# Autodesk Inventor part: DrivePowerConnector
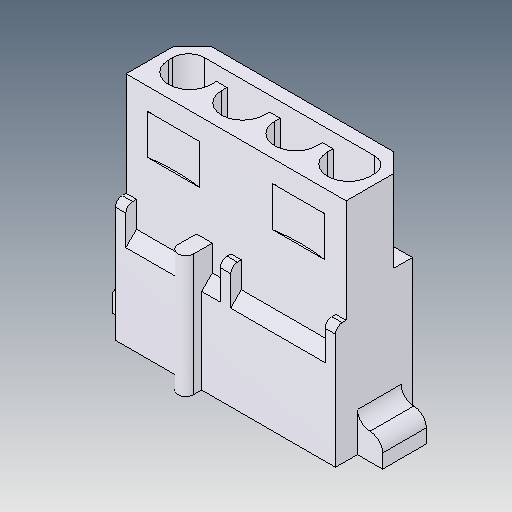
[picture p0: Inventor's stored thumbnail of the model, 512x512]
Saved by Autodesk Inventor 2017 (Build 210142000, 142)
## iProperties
Created: 2006-09
Part Number: DrivePowerConnector
Material: Generic
Document SubType Name: Modeling
Designer: DanielSeverino
Categories: <MemberInstance><Categories><Category DisplayName="" Mnemonic="CABLEANDHARNESS" InternalName="e4a7e005-5e42-4d16-b293-125e7f0d0512"><Category DisplayName="" Mne
Density: 1 g/cm^3
Appearance: Default
GlobalPropertyList: <PropertyList/>
Title: Drive Power Connector
Author: Prof. Daniel Severino
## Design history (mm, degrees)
feature "Solid1"
sketch "Sketch1"
  geometry: C1 r 1.125 at (9.9, -4.195) reference; C2 r 1.125 at (4.82, -4.195) reference; C3 r 1.125 at (-0.26, -4.195) reference; C4 r 1.125 at (-5.34, -4.195) reference; 5 further points
  constraints: 4 coincident
node "1"
node "2"
node "3"
node "4"
body "Solid2"
